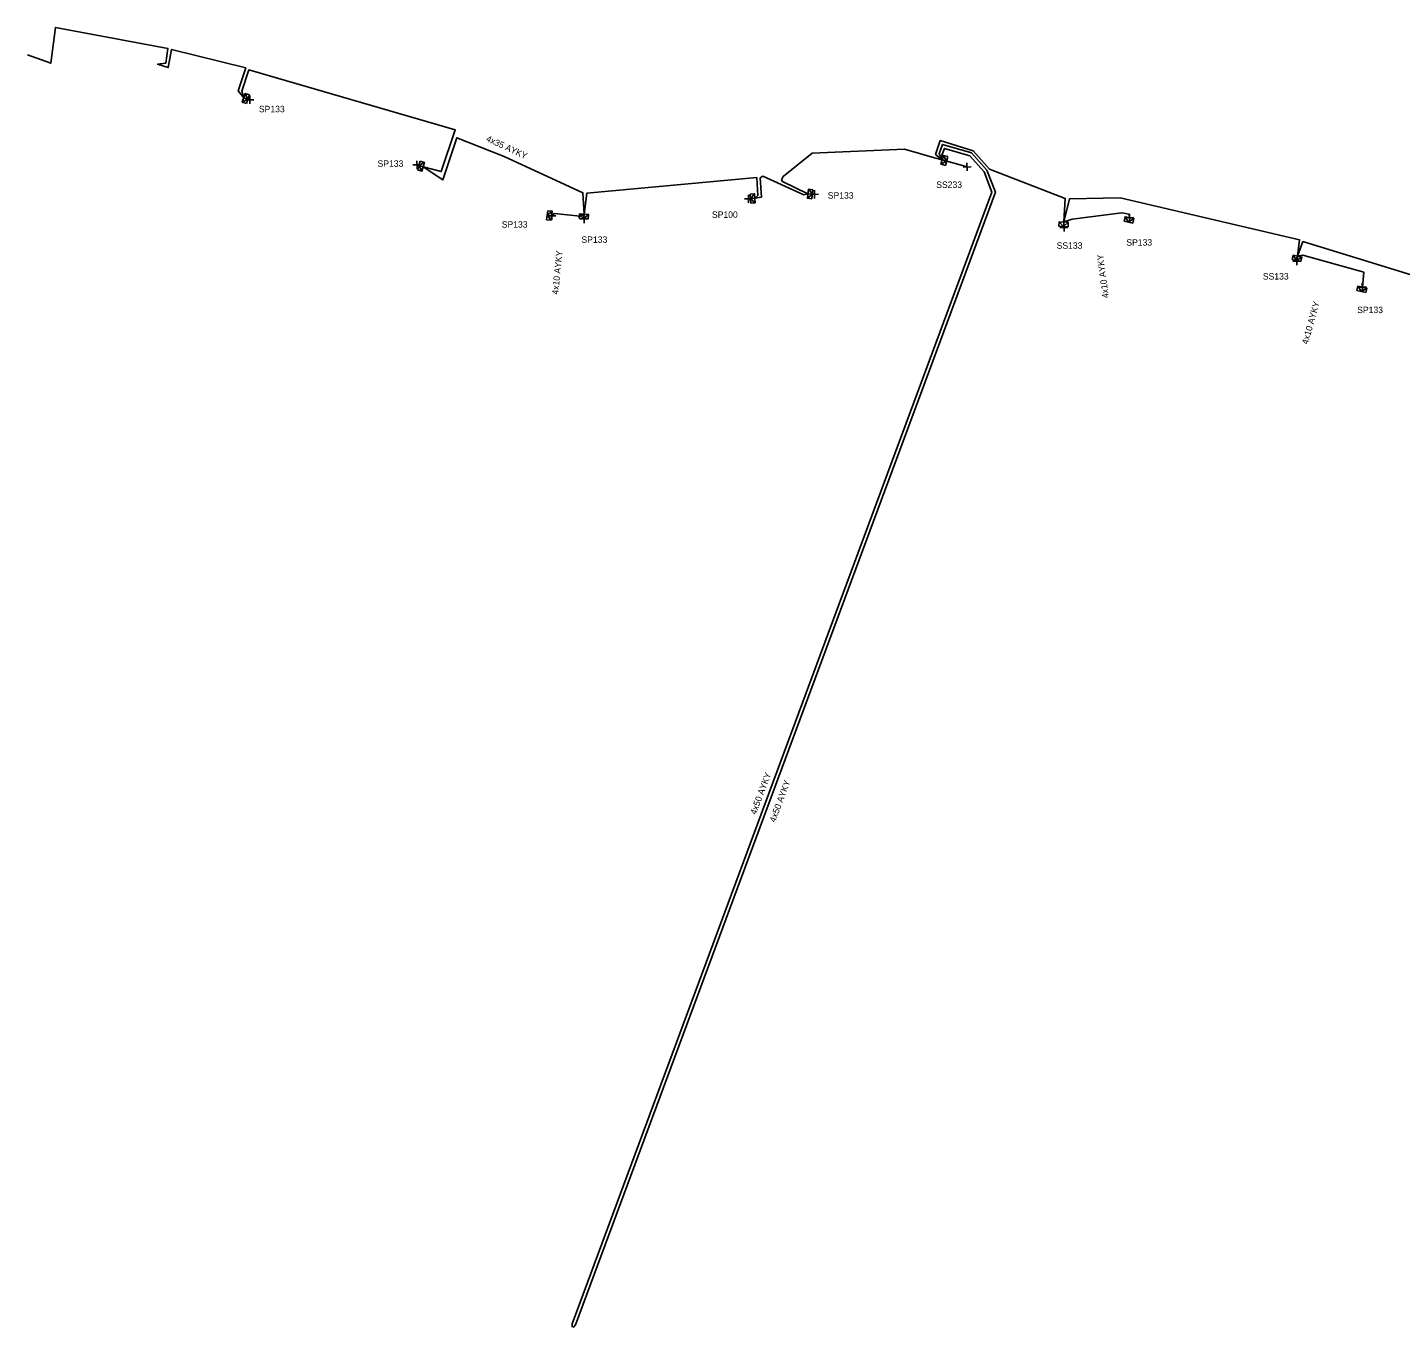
# Model space of a CAD drawing. Extents: x -762931 to -762496, y -1153652 to -1153451.
# Drawn here: x -762931.5 to -762719.1, y -1153651.9 to -1153451 of the extents above; entities that cross this region are included whole.
import ezdxf

# ---------------------------------------------------------------- set-up
doc = ezdxf.new("R2010")
doc.units = 0
for name, color, linetype in [('Vrstva 31', 7, 'Continuous'), ('Vrstva 33', 7, 'Continuous'), ('Vrstva 34', 7, 'Continuous'), ('Vrstva 5', 7, 'Continuous'), ('Vrstva 52', 7, 'Continuous'), ('Vrstva 54', 7, 'Continuous'), ('Vrstva 59', 7, 'Continuous'), ('Vrstva 6', 7, 'Continuous')]:
    doc.layers.add(name, color=color, linetype=linetype)

msp = doc.modelspace()

# ---------------------------------------------------------------- linework, layer by layer
at = {"layer": 'Vrstva 31'}
for points in [[(-762897.571, -1153462.715), (-762898.237, -1153462.499), (-762897.804, -1153461.168), (-762897.138, -1153461.384)], [(-762897.355, -1153462.05), (-762898.237, -1153462.499)], [(-762897.355, -1153462.05), (-762897.804, -1153461.168)], [(-762897.571, -1153462.715), (-762897.138, -1153461.384)], [(-762870.749, -1153471.611), (-762871.135, -1153472.957)], [(-762870.749, -1153471.611), (-762870.076, -1153471.804), (-762870.462, -1153473.15), (-762871.135, -1153472.957)], [(-762870.942, -1153472.284), (-762870.076, -1153471.804)], [(-762870.942, -1153472.284), (-762870.462, -1153473.15)], [(-762789.531, -1153472.268), (-762790.204, -1153472.075), (-762789.818, -1153470.73), (-762789.145, -1153470.923)], [(-762789.338, -1153471.596), (-762790.204, -1153472.075)], [(-762789.338, -1153471.596), (-762789.818, -1153470.73)], [(-762789.531, -1153472.268), (-762789.145, -1153470.923)], [(-762819.729, -1153476.72), (-762819.032, -1153476.659), (-762818.91, -1153478.054), (-762819.607, -1153478.115)], [(-762819.729, -1153476.72), (-762819.607, -1153478.115)], [(-762819.668, -1153477.418), (-762819.032, -1153476.659)], [(-762810.147, -1153477.422), (-762810.843, -1153477.349), (-762810.697, -1153475.957), (-762810, -1153476.03)], [(-762810.074, -1153476.726), (-762810.843, -1153477.349)], [(-762810.074, -1153476.726), (-762810.697, -1153475.957)], [(-762810.147, -1153477.422), (-762810, -1153476.03)], [(-762819.668, -1153477.418), (-762818.91, -1153478.054)], [(-762851.01, -1153479.277), (-762851.18, -1153480.666)], [(-762851.01, -1153479.277), (-762850.315, -1153479.362), (-762850.486, -1153480.751), (-762851.18, -1153480.666)], [(-762851.095, -1153479.971), (-762850.315, -1153479.362)], [(-762851.095, -1153479.971), (-762850.486, -1153480.751)], [(-762846.14, -1153480.449), (-762846.091, -1153479.751), (-762844.695, -1153479.849), (-762844.744, -1153480.547)], [(-762846.14, -1153480.449), (-762844.744, -1153480.547)], [(-762845.442, -1153480.498), (-762846.091, -1153479.751)], [(-762845.442, -1153480.498), (-762844.695, -1153479.849)], [(-762771.96, -1153481.669), (-762771.911, -1153480.971), (-762770.515, -1153481.069), (-762770.564, -1153481.767)], [(-762771.262, -1153481.718), (-762771.911, -1153480.971)], [(-762771.262, -1153481.718), (-762770.515, -1153481.069)], [(-762761.894, -1153480.899), (-762761.748, -1153480.214), (-762760.379, -1153480.505), (-762760.524, -1153481.19)], [(-762761.894, -1153480.899), (-762760.524, -1153481.19)], [(-762761.209, -1153481.044), (-762761.748, -1153480.214)], [(-762761.209, -1153481.044), (-762760.379, -1153480.505)], [(-762771.96, -1153481.669), (-762770.564, -1153481.767)], [(-762735.914, -1153486.839), (-762735.768, -1153486.154), (-762734.399, -1153486.445), (-762734.544, -1153487.13)], [(-762735.914, -1153486.839), (-762734.544, -1153487.13)], [(-762735.229, -1153486.984), (-762735.768, -1153486.154)], [(-762735.229, -1153486.984), (-762734.399, -1153486.445)], [(-762725.883, -1153491.629), (-762725.738, -1153490.944), (-762724.368, -1153491.236), (-762724.514, -1153491.92)], [(-762725.883, -1153491.629), (-762724.514, -1153491.92)], [(-762725.198, -1153491.775), (-762725.738, -1153490.944)], [(-762725.198, -1153491.775), (-762724.368, -1153491.236)]]:
    msp.add_lwpolyline(points, dxfattribs=at)
at = {"layer": 'Vrstva 34'}
for points in [[(-762897.695, -1153462.151), (-762896.445, -1153462.129)], [(-762897.059, -1153462.765), (-762897.081, -1153461.515)], [(-762871.845, -1153472.201), (-762870.595, -1153472.179)], [(-762871.209, -1153472.815), (-762871.231, -1153471.565)], [(-762786.795, -1153472.521), (-762785.545, -1153472.499)], [(-762786.159, -1153473.135), (-762786.181, -1153471.885)], [(-762819.949, -1153478.055), (-762819.971, -1153476.805)], [(-762810.395, -1153476.761), (-762809.145, -1153476.739)], [(-762809.759, -1153477.375), (-762809.781, -1153476.125)], [(-762820.585, -1153477.441), (-762819.335, -1153477.419)], [(-762851.025, -1153480.071), (-762849.775, -1153480.049)], [(-762850.389, -1153480.685), (-762850.411, -1153479.435)], [(-762846.025, -1153480.561), (-762844.775, -1153480.539)], [(-762845.389, -1153481.175), (-762845.411, -1153479.925)], [(-762771.179, -1153482.495), (-762771.201, -1153481.245)], [(-762761.685, -1153480.371), (-762760.435, -1153480.349)], [(-762761.049, -1153480.985), (-762761.071, -1153479.735)], [(-762771.815, -1153481.881), (-762770.565, -1153481.859)], [(-762735.805, -1153487.081), (-762734.555, -1153487.059)], [(-762735.169, -1153487.695), (-762735.191, -1153486.445)], [(-762725.675, -1153491.101), (-762724.425, -1153491.079)], [(-762725.039, -1153491.715), (-762725.061, -1153490.465)]]:
    msp.add_lwpolyline(points, dxfattribs=at)
at = {"layer": 'Vrstva 5'}
for points in [[(-762790.01, -1153471.4), (-762791.21, -1153471.12), (-762795.82, -1153469.77), (-762810.14, -1153470.39), (-762814.62, -1153473.98), (-762814.84, -1153474.52), (-762814.71, -1153474.74), (-762810.77, -1153476.65), (-762811.39, -1153476.82), (-762817.77, -1153473.94), (-762818.17, -1153474.21), (-762817.95, -1153477.18), (-762818.97, -1153477.36), (-762818.52, -1153476.91), (-762818.66, -1153474.16), (-762844.95, -1153476.56), (-762845.39, -1153479.8), (-762845.57, -1153476.51), (-762857.76, -1153470.88), (-762865.08, -1153468), (-762867.25, -1153474.52), (-762870.27, -1153472.48), (-762867.47, -1153473.23), (-762865.3, -1153466.8), (-762897.22, -1153457.52), (-762898.29, -1153460.81), (-762898.02, -1153461.83), (-762898.86, -1153460.76), (-762897.71, -1153457.22), (-762909.2, -1153454.38), (-762909.68, -1153457.17), (-762911.32, -1153456.64), (-762910.08, -1153456.5), (-762909.73, -1153454.2), (-762927.11, -1153450.96), (-762927.86, -1153456.5), (-762931.45, -1153455.17)], [(-762684.24, -1153505.63), (-762685.48, -1153505.11), (-762683.91, -1153500.67), (-762697.74, -1153495.71), (-762716.68, -1153489.45), (-762734.23, -1153484.04), (-762735.08, -1153486.3), (-762734.77, -1153483.77), (-762762.48, -1153477.29), (-762770.33, -1153477.43), (-762771.21, -1153481.02), (-762770.99, -1153477.38), (-762782.7, -1153472.86), (-762785.25, -1153470), (-762790.32, -1153468.44), (-762791.03, -1153470.57), (-762790.01, -1153471.4)], [(-762790.01, -1153471.4), (-762790.05, -1153470.7), (-762789.68, -1153469.64), (-762785.74, -1153470.79), (-762783.53, -1153473.26), (-762782.32, -1153476.43), (-762847.21, -1153651.29), (-762847.23, -1153651.81)], [(-762790.01, -1153471.4), (-762790.5, -1153470.51), (-762789.99, -1153469.02), (-762785.46, -1153470.35), (-762783.1, -1153472.99), (-762781.79, -1153476.43), (-762846.7, -1153651.42), (-762847.1, -1153651.86)]]:
    msp.add_lwpolyline(points, dxfattribs=at)
at = {"layer": 'Vrstva 52'}
for points in [[(-762845.39, -1153479.8), (-762845.97, -1153480.11), (-762850.01, -1153479.71), (-762850.4, -1153480.06)], [(-762771.21, -1153481.02), (-762769.93, -1153480.58), (-762762.23, -1153479.58), (-762761.1, -1153479.83), (-762761.06, -1153480.36)], [(-762735.08, -1153486.3), (-762734.23, -1153486.13), (-762724.83, -1153488.79), (-762725.05, -1153491.09)]]:
    msp.add_lwpolyline(points, dxfattribs=at)
at = {"layer": 'Vrstva 59'}
for points in [[(-762898.02, -1153461.83), (-762897.07, -1153462.14)], [(-762870.27, -1153472.48), (-762871.22, -1153472.19)], [(-762790.01, -1153471.4), (-762786.17, -1153472.51)], [(-762810.76, -1153476.65), (-762809.77, -1153476.75)], [(-762818.97, -1153477.36), (-762819.96, -1153477.43)], [(-762845.39, -1153479.8), (-762845.4, -1153480.55)], [(-762771.21, -1153481.02), (-762771.19, -1153481.87)], [(-762735.08, -1153486.3), (-762735.18, -1153487.07)]]:
    msp.add_lwpolyline(points, dxfattribs=at)

# ---------------------------------------------------------------- texts
at = {"layer": 'Vrstva 33'}
for s, p in [('SP133', (-762895.67, -1153464.06)), ('SP133', (-762877.32, -1153472.49)), ('SS233', (-762790.94, -1153475.75)), ('SP133', (-762807.71, -1153477.41)), ('SP133', (-762858.12, -1153481.89)), ('SP100', (-762825.62, -1153480.38)), ('SP133', (-762845.79, -1153484.24)), ('SS133', (-762772.32, -1153485.16)), ('SP133', (-762761.55, -1153484.67)), ('SS133', (-762740.44, -1153489.91)), ('SP133', (-762725.85, -1153495.1))]:
    msp.add_text(s, height=0.9943, dxfattribs=at).set_placement(p)
at = {"layer": 'Vrstva 54'}
for rotation, p in [(84.34847, (-762849.38, -1153492.27)), (97.39332, (-762764.25, -1153492.72)), (74.18871, (-762733.49, -1153500.01))]:
    msp.add_text('4x10 AYKY', height=0.9943, rotation=rotation, dxfattribs=at).set_placement(p)
at = {"layer": 'Vrstva 6'}
for s, rotation, p in [('4x35 AYKY', 335.20083, (-762860.63, -1153468.49)), ('4x50 AYKY', 69.6396, (-762818.81, -1153572.69)), ('4x50 AYKY', 69.64814, (-762815.84, -1153573.87))]:
    msp.add_text(s, height=0.9943, rotation=rotation, dxfattribs=at).set_placement(p)

doc.saveas('drawing.dxf')
